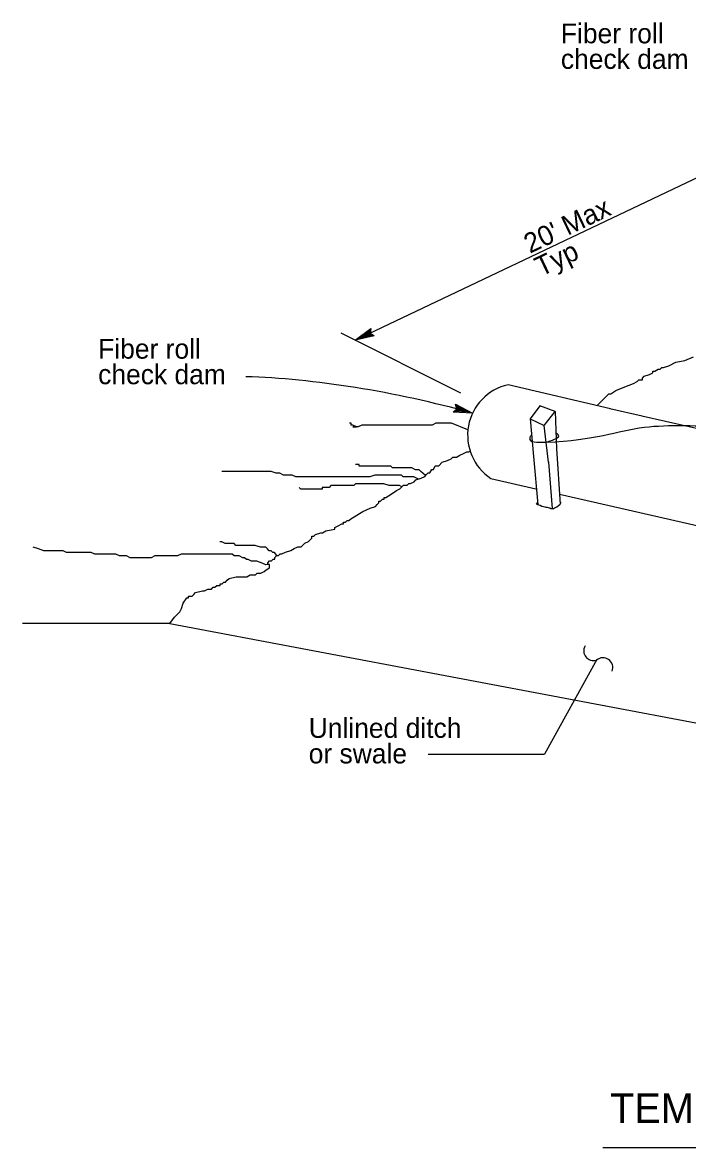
# Model space of a CAD drawing. Extents: x 6707415 to 6708768, y 1869893 to 1870831.
# Drawn here: x 6707442.1 to 6707644.1, y 1870028.6 to 1870370.2 of the extents above; entities that cross this region are included whole.
import ezdxf

# ---------------------------------------------------------------- set-up
doc = ezdxf.new("R2010")
doc.units = 0
for name, color, linetype in [('56 Stg 3 Anno', 7, 'Continuous'), ('57 Undefined', 7, 'Continuous'), ('60 Nongeo Data', 7, 'Continuous')]:
    doc.layers.add(name, color=color, linetype=linetype)

msp = doc.modelspace()

# ---------------------------------------------------------------- linework, layer by layer
at = {"layer": '56 Stg 3 Anno'}
for p, q in [((6707543.17, 1870273.7), (6707650.06, 1870324.6)), ((6707575.22, 1870257.62), (6707538.88, 1870275.86)), ((6707543.21, 1870273.72), (6707547.88, 1870277.33)), ((6707548.97, 1870275.01), (6707543.21, 1870273.72)), ((6707548.64, 1870275.23), (6707544.41, 1870274.28)), ((6707544.42, 1870274.29), (6707547.82, 1870276.92)), ((6707545.61, 1870274.85), (6707547.81, 1870276.54)), ((6707548.29, 1870275.44), (6707545.61, 1870274.85)), ((6707546.81, 1870275.41), (6707547.75, 1870276.14)), ((6707547.99, 1870275.67), (6707546.81, 1870275.41)), ((6707547.88, 1870277.33), (6707547.73, 1870275.84)), ((6707547.73, 1870275.84), (6707548.97, 1870275.01)), ((6707547.88, 1870277.33), (6707547.88, 1870277.33)), ((6707548.97, 1870275.01), (6707548.97, 1870275.01)), ((6707543.21, 1870273.72), (6707543.21, 1870273.72)), ((6707574.02, 1870252.9), (6707573.63, 1870254.35)), ((6707573.63, 1870254.35), (6707573.63, 1870254.35)), ((6707573.63, 1870254.35), (6707578.84, 1870251.57)), ((6707572.94, 1870251.88), (6707574.02, 1870252.9)), ((6707578.84, 1870251.57), (6707572.94, 1870251.88)), ((6707572.94, 1870251.88), (6707572.94, 1870251.88)), ((6707577.55, 1870251.93), (6707573.25, 1870252.15)), ((6707576.28, 1870252.28), (6707573.5, 1870252.42)), ((6707573.73, 1870253.96), (6707577.56, 1870251.93)), ((6707575, 1870252.64), (6707573.81, 1870252.7)), ((6707573.86, 1870253.57), (6707576.28, 1870252.28)), ((6707573.93, 1870253.2), (6707575, 1870252.64)), ((6707578.84, 1870251.57), (6707578.84, 1870251.57)), ((6707616.57, 1870176.79), (6707600.63, 1870148.08)), ((6707565.36, 1870148.03), (6707600.65, 1870148.03))]:
    msp.add_line(p, q, dxfattribs=at)
for centre, radius, start, end in [((6707615.56, 1870179.41), 2.96, 150.2525, 287.0948), ((6707618.43, 1870174.32), 2.99, 339.2494, 129.7493)]:
    msp.add_arc(centre, radius, start, end, dxfattribs=at)
msp.add_ellipse((6707561.4, 1870224.43), major_axis=(98.91, -24.01), ratio=0.301207, start_param=1.467078, end_param=2.189035, dxfattribs=at)
at = {"layer": '57 Undefined'}
msp.add_line((6707618.44, 1870028.6), (6707839.24, 1870028.6), dxfattribs=at)
at = {"layer": '60 Nongeo Data'}
for p, q in [((6707620.73, 1870252.94), (6707589.6, 1870260.2)), ((6707603.87, 1870252.13), (6707604.36, 1870240.74)), ((6707620.56, 1870252.98), (6707630.33, 1870250.78)), ((6707693.04, 1870236.28), (6707630.27, 1870250.69)), ((6707601.9, 1870236.74), (6707602.96, 1870222.66)), ((6707584.38, 1870231.74), (6707598.01, 1870228.62)), ((6707605.27, 1870226.96), (6707706.29, 1870203.89)), ((6707598.62, 1870223.85), (6707598.26, 1870224.31)), ((6707486.86, 1870187.72), (6707442.11, 1870187.72))]:
    msp.add_line(p, q, dxfattribs=at)
for points in [[(6707616.71, 1870253.88), (6707620.25, 1870257.42), (6707620.78, 1870257.42), (6707622.39, 1870258.49), (6707625.07, 1870259.56), (6707627.74, 1870260.63), (6707628.81, 1870261.16), (6707629.35, 1870261.7), (6707630.42, 1870261.7), (6707630.42, 1870262.23), (6707630.95, 1870262.76), (6707632.56, 1870263.3), (6707633.63, 1870263.83), (6707633.63, 1870264.37), (6707634.17, 1870264.37), (6707635.24, 1870264.9), (6707635.77, 1870264.9), (6707636.31, 1870265.44), (6707636.84, 1870265.44), (6707638.45, 1870265.97), (6707640.59, 1870267.04), (6707643.27, 1870267.57), (6707645.94, 1870268.64)], [(6707577.39, 1870246.49), (6707572.47, 1870248.52), (6707571.93, 1870248.52), (6707570.86, 1870248.52), (6707570.33, 1870248.52), (6707569.26, 1870248.52), (6707567.65, 1870248.52), (6707566.58, 1870247.98), (6707564.98, 1870247.98), (6707562.84, 1870247.98), (6707561.77, 1870247.98), (6707560.16, 1870247.98), (6707559.62, 1870247.98), (6707558.55, 1870247.98), (6707557.48, 1870247.98), (6707555.88, 1870247.98), (6707554.81, 1870247.98), (6707553.2, 1870247.98), (6707552.13, 1870247.98), (6707550.52, 1870247.98), (6707548.92, 1870247.98), (6707547.31, 1870247.98), (6707546.24, 1870247.98), (6707545.17, 1870247.98), (6707544.1, 1870247.45), (6707543.57, 1870247.45), (6707542.5, 1870247.45), (6707543.57, 1870247.45), (6707542.5, 1870247.98), (6707541.96, 1870247.98), (6707541.96, 1870248.52), (6707541.43, 1870248.52)], [(6707596.33, 1870249.84), (6707597.31, 1870238.38)], [(6707601.85, 1870236.76), (6707601.9, 1870236.74), (6707600.59, 1870247.87)], [(6707604.36, 1870240.74), (6707605.42, 1870223.98)], [(6707564.81, 1870232.91), (6707565.35, 1870233.44), (6707565.88, 1870233.44), (6707566.42, 1870234.51), (6707566.95, 1870234.51), (6707567.49, 1870235.58), (6707568.56, 1870235.58), (6707569.63, 1870236.65), (6707571.24, 1870237.18), (6707572.31, 1870237.72), (6707572.84, 1870238.25), (6707573.91, 1870238.25), (6707574.98, 1870238.79), (6707576.05, 1870239.32), (6707577.12, 1870239.85), (6707577.66, 1870239.85), (6707578.08, 1870240.06)], [(6707597.31, 1870238.38), (6707598.62, 1870223.85)], [(6707562.4, 1870231.57), (6707560.96, 1870232.26), (6707560.42, 1870232.26), (6707559.89, 1870232.26), (6707559.35, 1870232.26), (6707558.82, 1870232.26), (6707558.28, 1870232.26), (6707557.75, 1870232.26), (6707557.21, 1870232.79), (6707556.14, 1870232.79), (6707555.61, 1870232.79), (6707555.07, 1870232.79), (6707554, 1870232.79), (6707552.93, 1870232.79), (6707552.39, 1870232.79), (6707551.86, 1870232.79), (6707550.79, 1870232.79), (6707550.25, 1870232.79), (6707549.18, 1870232.79), (6707547.58, 1870232.26), (6707546.51, 1870232.26), (6707545.97, 1870232.26), (6707544.9, 1870232.26), (6707543.3, 1870232.26), (6707542.76, 1870232.26), (6707541.69, 1870232.26), (6707540.62, 1870232.26), (6707538.48, 1870232.26), (6707536.87, 1870232.26), (6707535.8, 1870232.26), (6707535.27, 1870232.26), (6707534.2, 1870232.26), (6707533.13, 1870232.26), (6707532.06, 1870232.26), (6707530.98, 1870232.26), (6707529.91, 1870232.26), (6707528.84, 1870232.26), (6707528.31, 1870232.26), (6707527.24, 1870232.26), (6707526.17, 1870232.26), (6707525.63, 1870232.26), (6707525.1, 1870232.26), (6707524.03, 1870232.79), (6707523.49, 1870232.79), (6707522.42, 1870232.79), (6707521.89, 1870232.79), (6707521.35, 1870232.79), (6707520.28, 1870233.33), (6707519.21, 1870233.33), (6707517.6, 1870233.86), (6707516.53, 1870233.86), (6707515.46, 1870233.86), (6707514.39, 1870233.86), (6707513.86, 1870233.86), (6707512.79, 1870233.86), (6707511.18, 1870233.86), (6707510.11, 1870233.86), (6707509.04, 1870233.86), (6707507.97, 1870233.86), (6707507.43, 1870233.86), (6707506.9, 1870233.86), (6707506.36, 1870233.86), (6707505.83, 1870233.86), (6707505.29, 1870233.86), (6707504.22, 1870233.86), (6707503.15, 1870233.86), (6707503.15, 1870233.86), (6707502.62, 1870233.86)], [(6707564.54, 1870232.64), (6707563.1, 1870233.86), (6707562.56, 1870234.4), (6707562.03, 1870234.4), (6707561.49, 1870234.4), (6707560.42, 1870234.93), (6707559.89, 1870234.93), (6707559.35, 1870234.93), (6707558.82, 1870234.93), (6707558.28, 1870234.93), (6707557.75, 1870234.93), (6707557.21, 1870234.93), (6707556.68, 1870234.93), (6707556.14, 1870234.93), (6707555.61, 1870234.93), (6707555.07, 1870234.93), (6707554.54, 1870234.93), (6707554, 1870235.46), (6707552.93, 1870235.46), (6707552.39, 1870235.46), (6707551.86, 1870235.46), (6707551.32, 1870235.46), (6707550.25, 1870235.46), (6707549.18, 1870235.46), (6707548.65, 1870235.46), (6707548.11, 1870235.46), (6707547.04, 1870235.46), (6707546.51, 1870235.46), (6707545.97, 1870235.46), (6707545.44, 1870235.46), (6707544.9, 1870235.46), (6707544.37, 1870235.46), (6707544.37, 1870235.46), (6707544.37, 1870236), (6707543.83, 1870236), (6707543.3, 1870236)], [(6707486.86, 1870187.72), (6707488.27, 1870189.61), (6707489.88, 1870191.22), (6707490.41, 1870192.28), (6707490.95, 1870193.89), (6707492.02, 1870195.49), (6707492.55, 1870195.49), (6707492.55, 1870196.03), (6707493.62, 1870196.03), (6707494.16, 1870196.56), (6707494.69, 1870197.09), (6707496.83, 1870197.63), (6707497.37, 1870197.63), (6707498.44, 1870198.16), (6707499.51, 1870198.16), (6707500.05, 1870198.7), (6707500.58, 1870198.7), (6707501.12, 1870199.23), (6707501.65, 1870199.23), (6707502.19, 1870199.23), (6707502.19, 1870199.77), (6707502.72, 1870199.77), (6707503.26, 1870200.3), (6707503.79, 1870200.3), (6707504.33, 1870200.84), (6707504.86, 1870201.37), (6707507, 1870201.91), (6707508.61, 1870201.91), (6707510.22, 1870201.91), (6707511.29, 1870202.44), (6707512.89, 1870202.44), (6707513.43, 1870202.97), (6707514.5, 1870202.97), (6707515.57, 1870203.51), (6707516.1, 1870204.04), (6707517.17, 1870204.58), (6707517.17, 1870205.11), (6707517.17, 1870205.65), (6707516.64, 1870205.65), (6707516.64, 1870206.18), (6707517.17, 1870206.72), (6707517.71, 1870206.72), (6707518.24, 1870207.25), (6707518.78, 1870207.25), (6707518.78, 1870207.78), (6707519.32, 1870208.32), (6707519.85, 1870208.32), (6707520.39, 1870208.85), (6707520.92, 1870208.85), (6707521.99, 1870209.39), (6707523.6, 1870209.92), (6707524.67, 1870210.46), (6707525.74, 1870210.99), (6707526.81, 1870210.99), (6707527.88, 1870212.06), (6707528.95, 1870212.6), (6707529.49, 1870213.13), (6707530.02, 1870213.66), (6707530.02, 1870214.2), (6707530.56, 1870214.2), (6707531.09, 1870214.73), (6707532.7, 1870215.27), (6707533.23, 1870215.27), (6707534.3, 1870215.8), (6707536.98, 1870216.34), (6707536.98, 1870216.87), (6707538.05, 1870217.41), (6707539.12, 1870217.94), (6707539.66, 1870217.94), (6707539.66, 1870218.47), (6707540.19, 1870218.47), (6707540.73, 1870219.01), (6707541.26, 1870219.01), (6707541.8, 1870219.54), (6707542.87, 1870220.08), (6707544.47, 1870221.15), (6707545.54, 1870221.68), (6707547.68, 1870222.75), (6707549.29, 1870223.28), (6707549.82, 1870223.82), (6707550.36, 1870224.35), (6707550.36, 1870224.89), (6707550.9, 1870224.89), (6707551.43, 1870225.42), (6707551.97, 1870225.42), (6707551.97, 1870225.96), (6707552.5, 1870225.96), (6707554.11, 1870227.03), (6707555.71, 1870228.1), (6707556.78, 1870228.63), (6707557.32, 1870229.16), (6707557.85, 1870229.7), (6707558.39, 1870229.7), (6707558.92, 1870229.7), (6707559.46, 1870230.23), (6707559.99, 1870230.23), (6707561.07, 1870230.77), (6707561.6, 1870231.3), (6707563.21, 1870231.84), (6707564.28, 1870232.37), (6707564.81, 1870232.91)], [(6707557.32, 1870229.16), (6707556.68, 1870229.58), (6707556.14, 1870229.58), (6707555.07, 1870229.58), (6707553.47, 1870229.58), (6707551.86, 1870230.12), (6707550.79, 1870230.12), (6707550.25, 1870230.12), (6707548.65, 1870230.12), (6707548.11, 1870230.12), (6707547.04, 1870230.12), (6707546.51, 1870230.12), (6707545.97, 1870230.12), (6707545.44, 1870230.12), (6707543.83, 1870230.12), (6707543.3, 1870230.12), (6707542.76, 1870229.58), (6707542.23, 1870229.58), (6707541.69, 1870229.58), (6707541.15, 1870229.58), (6707540.62, 1870229.58), (6707539.55, 1870229.58), (6707539.01, 1870229.58), (6707538.48, 1870229.58), (6707537.94, 1870229.58), (6707536.87, 1870229.58), (6707535.8, 1870229.58), (6707535.27, 1870229.05), (6707534.73, 1870229.05), (6707533.66, 1870229.05), (6707533.13, 1870229.05), (6707533.13, 1870228.52), (6707532.59, 1870228.52), (6707532.06, 1870228.52), (6707531.52, 1870228.52), (6707530.98, 1870228.52), (6707529.91, 1870228.52), (6707529.38, 1870228.52), (6707528.84, 1870228.52), (6707527.77, 1870228.52), (6707526.7, 1870228.52), (6707526.7, 1870228.52), (6707526.17, 1870229.05)], [(6707598.21, 1870223.98), (6707598.57, 1870223.86), (6707599.41, 1870223.62), (6707599.89, 1870223.38), (6707600.01, 1870223.38), (6707600.37, 1870223.26), (6707600.74, 1870223.14), (6707601.1, 1870223.02), (6707601.46, 1870223.02), (6707601.82, 1870222.9), (6707602.06, 1870222.78), (6707602.42, 1870222.78), (6707602.54, 1870222.66), (6707602.66, 1870222.66), (6707603.14, 1870222.66), (6707603.26, 1870222.54), (6707603.38, 1870222.66), (6707603.74, 1870222.78), (6707604.49, 1870223.15)], [(6707604.47, 1870223.14), (6707604.95, 1870223.5), (6707605.31, 1870223.86), (6707605.43, 1870223.98), (6707605.55, 1870224.1), (6707605.67, 1870224.46), (6707605.79, 1870224.46), (6707605.79, 1870224.46), (6707605.67, 1870224.46)], [(6707516.64, 1870205.65), (6707516, 1870205.53), (6707514.93, 1870206.07), (6707513.32, 1870206.6), (6707511.72, 1870206.6), (6707510.64, 1870207.14), (6707510.11, 1870207.14), (6707509.57, 1870207.67), (6707509.04, 1870207.67), (6707507.97, 1870208.21), (6707507.43, 1870208.21), (6707506.36, 1870208.21), (6707505.83, 1870208.74), (6707505.29, 1870208.74), (6707504.22, 1870208.74), (6707503.15, 1870208.74), (6707502.62, 1870208.74), (6707501.55, 1870208.74), (6707501.01, 1870208.74), (6707499.94, 1870208.74), (6707499.4, 1870208.74), (6707498.33, 1870208.74), (6707497.26, 1870208.74), (6707496.19, 1870208.74), (6707494.59, 1870208.74), (6707494.05, 1870208.74), (6707492.98, 1870208.74), (6707491.91, 1870208.74), (6707490.31, 1870208.74), (6707489.23, 1870208.21), (6707488.16, 1870208.21), (6707487.63, 1870208.21), (6707487.09, 1870208.21), (6707486.02, 1870208.21), (6707484.42, 1870208.21), (6707483.35, 1870208.21), (6707482.28, 1870208.21), (6707481.21, 1870207.67), (6707480.14, 1870207.67), (6707479.6, 1870207.67), (6707479.06, 1870207.67), (6707477.99, 1870207.67), (6707477.46, 1870207.67), (6707476.39, 1870207.67), (6707475.85, 1870207.67), (6707474.78, 1870207.67), (6707473.71, 1870208.21), (6707473.18, 1870208.21), (6707471.57, 1870208.21), (6707470.5, 1870208.74), (6707469.97, 1870208.74), (6707469.43, 1870208.74), (6707468.89, 1870208.74), (6707467.82, 1870208.74), (6707467.29, 1870208.74), (6707466.75, 1870208.74), (6707466.22, 1870208.74), (6707465.15, 1870208.74), (6707464.08, 1870208.74), (6707463.01, 1870209.27), (6707461.4, 1870209.27), (6707460.33, 1870209.27), (6707459.8, 1870209.27), (6707458.73, 1870209.27), (6707458.19, 1870209.27), (6707457.65, 1870209.27), (6707456.58, 1870209.27), (6707455.51, 1870209.27), (6707454.44, 1870209.81), (6707453.37, 1870209.81), (6707452.84, 1870209.81), (6707452.3, 1870209.81), (6707451.77, 1870209.81), (6707450.7, 1870209.81), (6707450.16, 1870209.81), (6707449.63, 1870209.81), (6707449.09, 1870209.81), (6707449.09, 1870209.81), (6707448.56, 1870209.81), (6707446.95, 1870210.34), (6707445.34, 1870210.88)], [(6707519.32, 1870208.32), (6707518.67, 1870209.27), (6707518.14, 1870209.27), (6707517.6, 1870209.81), (6707517.07, 1870209.81), (6707516.53, 1870210.34), (6707516, 1870210.88), (6707515.46, 1870210.88), (6707514.39, 1870210.88), (6707512.79, 1870211.41), (6707511.72, 1870211.41), (6707511.18, 1870211.41), (6707510.64, 1870211.41), (6707510.11, 1870211.41), (6707509.04, 1870211.41), (6707508.5, 1870211.41), (6707507.43, 1870211.41), (6707506.9, 1870211.41), (6707506.36, 1870211.95), (6707505.83, 1870211.95), (6707505.29, 1870211.95), (6707504.76, 1870211.95), (6707503.69, 1870211.95), (6707503.69, 1870211.95), (6707502.62, 1870212.48), (6707502.08, 1870212.48)], [(6707486.86, 1870187.72), (6707695.92, 1870148.21)]]:
    msp.add_lwpolyline(points, dxfattribs=at)
msp.add_lwpolyline([(6707596.33, 1870249.84), (6707600.59, 1870247.87), (6707603.87, 1870252.13), (6707599.28, 1870253.77)], close=True, dxfattribs=at)
msp.add_arc((6707593.06, 1870244.86), 15.73, 102.7086, 236.5226, dxfattribs=at)
for points in [[(6707596.58, 1870244.84), (6707596.19, 1870244.06), (6707601.24, 1870242.77), (6707631.03, 1870247.3), (6707656.67, 1870247.3)], [(6707601.63, 1870242.9), (6707604.86, 1870244.97), (6707604.35, 1870245.36)]]:
    msp.add_spline(points, degree=3, dxfattribs=at)

# ---------------------------------------------------------------- texts
at = {"layer": '57 Undefined'}
for s, height, p in [('Fiber roll ', 6, (6707605.65, 1870363.88)), ('check dam', 6, (6707605.65, 1870356.11)), ('Fiber roll ', 6, (6707465.09, 1870268.12)), ('check dam', 6, (6707465.09, 1870260.36)), ('Unlined ditch ', 6, (6707529.05, 1870152.98)), ('or swale', 6, (6707529.05, 1870145.22)), ('TEMPORARY CHECK DAM (TYPE 1)', 9, (6707620.63, 1870036.08))]:
    msp.add_text(s, height=height, dxfattribs=at).set_placement(p)
for s, p in [("20' Max", (6707596.24, 1870299.95)), ('Typ', (6707599.58, 1870292.94))]:
    msp.add_text(s, height=6, rotation=25.4626, dxfattribs=at).set_placement(p)

doc.saveas('drawing.dxf')
